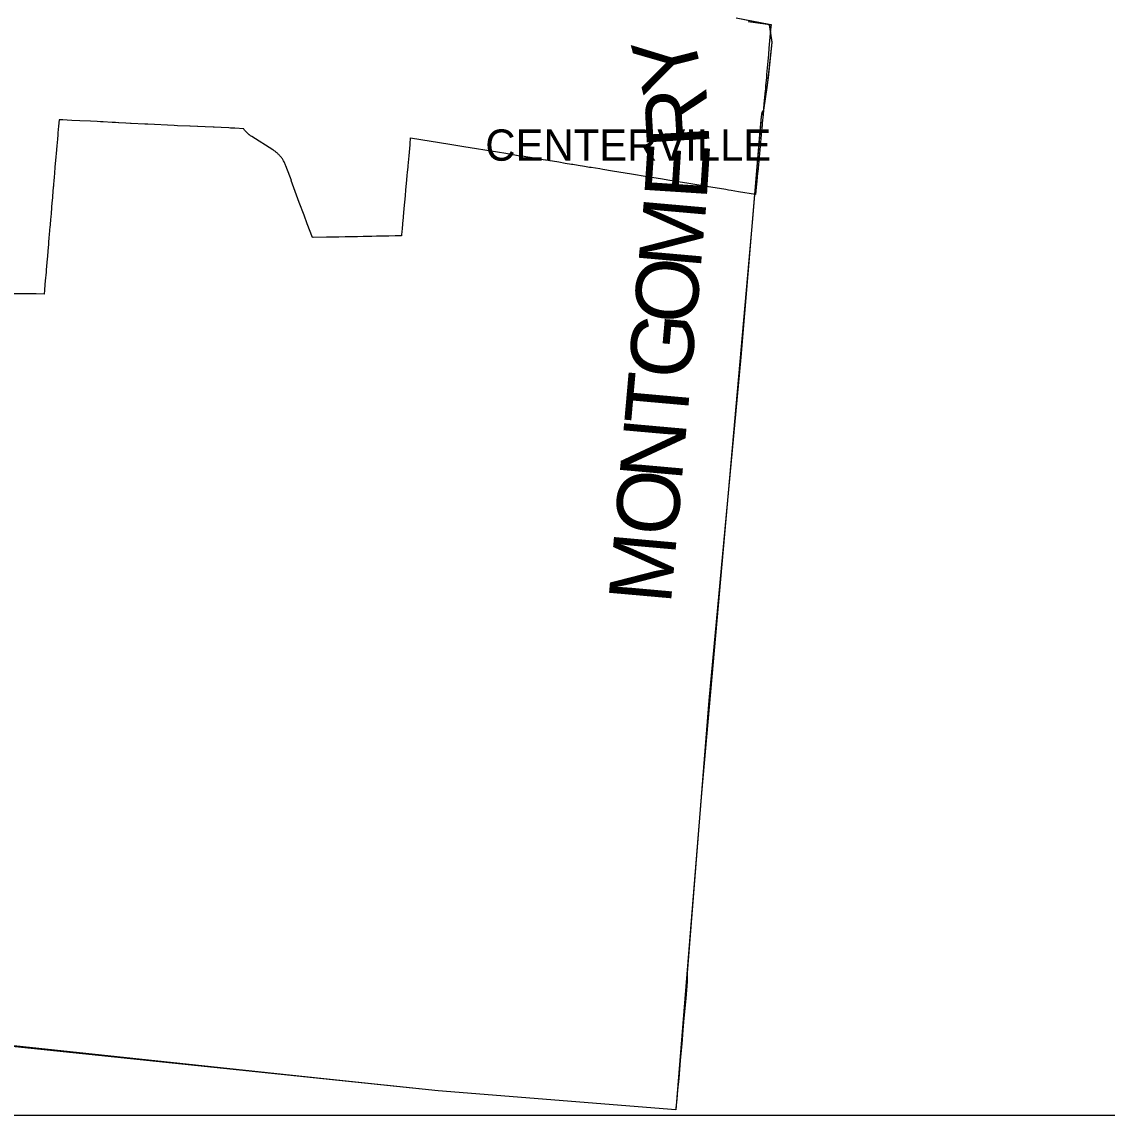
# Model space of a CAD drawing. Extents: x 0 to 34, y 0 to 22.
# Drawn here: x 5.4643 to 5.7431, y 14.1 to 14.3807 of the extents above; entities that cross this region are included whole.
import ezdxf

# ---------------------------------------------------------------- set-up
doc = ezdxf.new("R2010")
doc.units = 0
for name, color, linetype in [('GM_X_Corporation', 7, 'Continuous'), ('GM_X_Corporation_Text', 7, 'Continuous'), ('GM_X_County', 7, 'Continuous'), ('GM_X_County_Text', 7, 'Continuous'), ('SC_Scratch1', 7, 'Continuous'), ('SH_Data', 7, 'Continuous')]:
    doc.layers.add(name, color=color, linetype=linetype)

msp = doc.modelspace()

# ---------------------------------------------------------------- linework, layer by layer
at = {"layer": 'GM_X_Corporation'}
msp.add_lwpolyline([(5.65087, 14.38083), (5.65583, 14.38013), (5.65632, 14.38007), (5.65679, 14.38), (5.65667, 14.37866), (5.65624, 14.37393), (5.6561, 14.37231), (5.65564, 14.3672), (5.65557, 14.36638), (5.65538, 14.36429), (5.65531, 14.36348), (5.65527, 14.36301), (5.65504, 14.36048), (5.65487, 14.35854), (5.65482, 14.35803), (5.65472, 14.35696), (5.65452, 14.35469), (5.65446, 14.354), (5.65442, 14.3536), (5.65435, 14.35273), (5.65417, 14.35079), (5.65408, 14.34977), (5.65334, 14.34219), (5.65331, 14.34184), (5.65312, 14.33981), (5.65296, 14.33823), (5.65279, 14.33639), (5.64839, 14.3371), (5.64649, 14.33741), (5.64586, 14.33752), (5.64519, 14.33763), (5.64021, 14.33844), (5.63872, 14.33868), (5.63869, 14.33869), (5.63512, 14.33927), (5.6334, 14.33955), (5.63303, 14.33961), (5.63079, 14.33998), (5.62838, 14.34037), (5.62492, 14.34094), (5.62091, 14.34159), (5.616, 14.3424), (5.61354, 14.3428), (5.61275, 14.34293), (5.61053, 14.34329), (5.61015, 14.34335), (5.60886, 14.34356), (5.6072, 14.34384), (5.60583, 14.34406), (5.60553, 14.34411), (5.60386, 14.34438), (5.60223, 14.34465), (5.6006, 14.34492), (5.60003, 14.34501), (5.5999, 14.34503), (5.59896, 14.34519), (5.5988, 14.34521), (5.59712, 14.34549), (5.59704, 14.3455), (5.59616, 14.34564), (5.59538, 14.34577), (5.59379, 14.34603), (5.59336, 14.3461), (5.59184, 14.34635), (5.59139, 14.34642), (5.58864, 14.34687), (5.58652, 14.34721), (5.57783, 14.34863), (5.57422, 14.34922), (5.56412, 14.35088), (5.5641, 14.35089), (5.56396, 14.34936), (5.56395, 14.34928), (5.56394, 14.34914), (5.56369, 14.34635), (5.56345, 14.34373), (5.56334, 14.34246), (5.56333, 14.34232), (5.56332, 14.34221), (5.56322, 14.34117), (5.56305, 14.33921), (5.5629, 14.33761), (5.56276, 14.336), (5.56261, 14.3344), (5.56247, 14.3328), (5.56228, 14.33064), (5.56225, 14.33031), (5.5622, 14.32984), (5.56201, 14.32768), (5.56193, 14.32683), (5.56186, 14.32608), (5.56186, 14.32602), (5.56184, 14.32576), (5.56021, 14.32573), (5.55861, 14.3257), (5.557, 14.32567), (5.55539, 14.32564), (5.55422, 14.32562), (5.55378, 14.32561), (5.55218, 14.32558), (5.55203, 14.32558), (5.55057, 14.32555), (5.54969, 14.32553), (5.54896, 14.32552), (5.54736, 14.32549), (5.54575, 14.32546), (5.54414, 14.32543), (5.54253, 14.3254), (5.53916, 14.32533), (5.53897, 14.32533), (5.53762, 14.32887), (5.53681, 14.33104), (5.53559, 14.33434), (5.53349, 14.33996), (5.53348, 14.33998), (5.53354, 14.34), (5.53329, 14.34067), (5.53256, 14.34263), (5.53214, 14.34374), (5.53206, 14.34395), (5.53196, 14.34419), (5.53187, 14.34438), (5.53178, 14.34458), (5.53167, 14.34479), (5.53155, 14.34499), (5.53144, 14.34517), (5.53134, 14.34534), (5.53123, 14.34551), (5.5311, 14.34569), (5.53098, 14.34585), (5.53085, 14.34602), (5.53074, 14.34615), (5.5306, 14.34631), (5.53049, 14.34643), (5.53038, 14.34655), (5.53029, 14.34664), (5.53018, 14.34675), (5.53007, 14.34686), (5.52995, 14.34697), (5.52981, 14.34709), (5.5297, 14.34719), (5.52958, 14.34729), (5.52945, 14.34739), (5.52931, 14.3475), (5.52913, 14.34762), (5.52897, 14.34773), (5.52881, 14.34784), (5.52335, 14.35127), (5.52318, 14.35138), (5.52307, 14.35145), (5.52297, 14.35153), (5.52288, 14.3516), (5.52279, 14.35166), (5.5227, 14.35173), (5.5226, 14.35181), (5.5225, 14.35189), (5.52243, 14.35196), (5.52235, 14.35203), (5.52226, 14.35211), (5.52217, 14.3522), (5.52209, 14.35228), (5.52201, 14.35236), (5.52193, 14.35244), (5.52185, 14.35253), (5.52179, 14.3526), (5.52172, 14.35268), (5.52164, 14.35277), (5.52158, 14.35285), (5.52151, 14.35294), (5.52144, 14.35303), (5.52135, 14.35315), (5.5213, 14.35323), (5.51902, 14.3534), (5.51867, 14.35342), (5.51798, 14.35345), (5.51789, 14.35345), (5.51748, 14.35347), (5.51547, 14.35356), (5.51369, 14.35363), (5.51346, 14.35364), (5.51144, 14.35373), (5.50954, 14.35381), (5.50943, 14.35382), (5.50755, 14.3539), (5.50742, 14.3539), (5.50425, 14.35404), (5.50344, 14.35407), (5.49665, 14.35442), (5.49593, 14.35446), (5.4924, 14.35464), (5.49223, 14.35465), (5.491, 14.35471), (5.48919, 14.35481), (5.4891, 14.35481), (5.48839, 14.35485), (5.48751, 14.35489), (5.48518, 14.35501), (5.48477, 14.35503), (5.48447, 14.35505), (5.48365, 14.35509), (5.48197, 14.35518), (5.4792, 14.35532), (5.47715, 14.35542), (5.47591, 14.35549), (5.47481, 14.35554), (5.47386, 14.35559), (5.47372, 14.35391), (5.47357, 14.35223), (5.47353, 14.35169), (5.47343, 14.35055), (5.47328, 14.34887), (5.47312, 14.34688), (5.47305, 14.34608), (5.47281, 14.34336), (5.47268, 14.34183), (5.4726, 14.34082), (5.47252, 14.3399), (5.47251, 14.33975), (5.47246, 14.33917), (5.47244, 14.339), (5.47241, 14.33862), (5.4724, 14.33855), (5.47238, 14.33823), (5.47219, 14.33599), (5.47216, 14.33567), (5.47215, 14.33552), (5.47203, 14.33421), (5.47194, 14.33311), (5.47192, 14.3329), (5.47181, 14.33158), (5.47172, 14.33054), (5.47168, 14.33008), (5.47155, 14.32858), (5.4715, 14.32798), (5.47144, 14.32727), (5.47133, 14.32595), (5.47128, 14.32542), (5.47116, 14.32399), (5.47112, 14.32352), (5.47099, 14.32193), (5.47086, 14.32045), (5.47081, 14.31985), (5.47057, 14.31704), (5.47052, 14.31644), (5.47033, 14.31425), (5.47025, 14.31327), (5.47012, 14.3118), (5.47004, 14.31083), (5.468, 14.31084), (5.4602, 14.31087)], dxfattribs=at)
at = {"layer": 'GM_X_County'}
msp.add_lwpolyline([(5.64782, 14.38178), (5.6563, 14.38009), (5.65694, 14.37548), (5.65578, 14.36449), (5.65483, 14.358), (5.65475, 14.35791), (5.65468, 14.35783), (5.65462, 14.35776), (5.65457, 14.35768), (5.65453, 14.35761), (5.65448, 14.35752), (5.65444, 14.35744), (5.65441, 14.35733), (5.65437, 14.35724), (5.65435, 14.35713), (5.65433, 14.35704), (5.65431, 14.35687), (5.65428, 14.35664), (5.65426, 14.3564), (5.65404, 14.35405), (5.65264, 14.33737), (5.64905, 14.29465), (5.64077, 14.20647), (5.63526, 14.13651), (5.63522, 14.13431), (5.63485, 14.12998), (5.63456, 14.12657), (5.63432, 14.12395), (5.63412, 14.1218), (5.63392, 14.11939), (5.63381, 14.11829), (5.63342, 14.11399), (5.63323, 14.11173), (5.63304, 14.10941), (5.63278, 14.10637), (5.63256, 14.10402), (5.63249, 14.1033), (5.63235, 14.10183), (5.63231, 14.10134), (5.57125, 14.10622), (5.54353, 14.10916), (5.43403, 14.12076)], dxfattribs=at)
at = {"layer": 'SC_Scratch1'}
msp.add_lwpolyline([(5.64782, 14.38178), (5.65607, 14.38013), (5.65632, 14.37998), (5.65693, 14.37543), (5.65599, 14.36641), (5.65545, 14.36222), (5.65483, 14.358), (5.65426, 14.3564), (5.65376, 14.35074), (5.65203, 14.33016), (5.6389, 14.18271), (5.63231, 14.10134), (5.63233, 14.10134), (5.57127, 14.10622), (4.8533, 14.18087)], dxfattribs=at)
at = {"layer": 'SH_Data'}
msp.add_line((2.1, 14.1), (8.9, 14.1), dxfattribs=at)

# ---------------------------------------------------------------- texts
at = {"layer": 'GM_X_Corporation_Text'}
msp.add_text('CENTERVILLE', height=0.008037, rotation=0, dxfattribs=at).set_placement((5.58337, 14.34505))
at = {"layer": 'GM_X_County_Text'}
for s, rotation, p in [('Y', 104.2391, (5.63972, 14.36529)), ('R', 93.3828, (5.641, 14.34895)), ('E', 86.2973, (5.64022, 14.33478)), ('M', 84.9677, (5.63866, 14.31697)), ('O', 84.9163, (5.6374, 14.3028)), ('G', 84.9167, (5.63614, 14.28864)), ('T', 84.9149, (5.63507, 14.27666)), ('N', 84.9156, (5.63381, 14.2625)), ('O', 84.9156, (5.63255, 14.24834)), ('M', 84.9159, (5.631, 14.23094))]:
    msp.add_text(s, height=0.01607, rotation=rotation, dxfattribs=at).set_placement(p)

doc.saveas('drawing.dxf')
